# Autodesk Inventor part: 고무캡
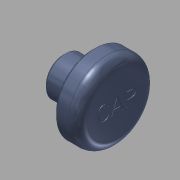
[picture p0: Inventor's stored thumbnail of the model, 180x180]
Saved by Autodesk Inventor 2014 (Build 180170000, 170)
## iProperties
Created: 2017-06
Part Number: 고무캡
Material: 고무
Document SubType Name: Modeling
Designer: mduedu
Density: 1 g/cm^3
Appearance: 고무 - 파란색 - 버전 1.1
Author: mduedu
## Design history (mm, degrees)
sketch "스케치1"
  geometry: L1 (0, 0)-(11, 0); L2 (11, 0)-(11, 8); L3 (11, 8)-(6.5, 8); L4 (0, 4)-(0, 0); L5 (0, 4)-(6, 4); L6 (6, 4)-(6, 7.5); L7 (6, 7.5)-(6.5, 7.5); L8 (6.5, 7.5)-(6.5, 8)
  constraints: 16 end point, 2 horizontal, 2 parallel, 2 perpendicular, 2 point on line, 1 vertical
  dimensions: "d0" = 16 diameter of L3 L1; "d2" = 8 diameter of L5 L1; "d6" = 5 distance between parallel lines of L2 L6; "d7" = 0.5 distance between parallel lines of L8 L6; "d8" = 15 diameter of L7 L1; "d9" = 6 distance between parallel lines of L6 L4
revolve "회전1" sketch "스케치1" stored, may be unused: angle "d10" = 90 deg
hole "구멍1" diameter "d22" = 5; stored, may be unused: countersink angle "d26" = 90 deg, drill point angle "d28" = 0 deg; dims "d23" = 6, "d24" = 4, "d25" = 2, "d27" = 6, "d30" = 10, "d31" = 10
chamfer "모따기1" distance "d13" = 0.5; stored, may be unused: second distance "d14" = 2, angle "d15" = 45 deg
fillet "모깎기3" dims "d29" = 1
fillet "모깎기1" dims "d16" = 0.1
fillet "모깎기2" dims "d17" = 2
sketch "스케치3"
  geometry: 2 further points
  constraints: 1 coincident, 1 other
feature "엠보싱1" sketch "스케치3" dims "d18" = 0.2, "d19" = 0
node "솔리드1"
